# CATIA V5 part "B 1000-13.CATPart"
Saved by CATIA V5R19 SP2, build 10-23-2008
Part number: B 1000-13
Bounding box of the stored display mesh (mm): x -24.865 to 24.865, y -24.997 to 24.997, z 0 to 120.4
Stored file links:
  C:\Users\Bora\Desktop\3D Katı model\B serisi\B 1000\B 1000-13.CATPart
  C:\Program Files\Dassault Systemes\B19\intel_a\reffiles\standard\MetricThickPitch.txt
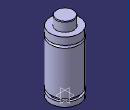
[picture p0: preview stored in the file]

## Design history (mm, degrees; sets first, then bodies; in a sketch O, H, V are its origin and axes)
Body1 (main body)
  Sketch1 on yz-plane, origin (0, 0, 0), H (0, 1, 0), V (0, 0, 1)
    point P3 (15, 119.4)
    point P5 (15, 119.4)
    point P10 (25, 87.9)
    point P11 (25, 91.9)
    point P13 (25, 91.9)
    point P14 (25, 87.9)
    line L1 (25, 0) -> (25, 8)
    line L2 (15, 119.4) -> (15, 104.4)
    arc A1 centre (14, 119.4) radius 1 from (15, 119.4) to (14, 120.4) ccw
    line L3 (21.5, 13) -> (21.5, 8)
    line L4 (25, 13) -> (25, 87.9)
    line L5 (25, 91.9) -> (25, 104.4)
    arc A2 centre (25, 89.9) radius 2 from (25, 91.9) to (25, 87.9) ccw
    line L6 (14, 120.4) -> (0, 120.4)
    point P15 (0, 120.4)
    line L7 (15, 104.4) -> (25, 104.4)
    line L8 (0, 0) -> (25, 0)
    line L9 (21.5, 13) -> (25, 13)
    line L10 (21.5, 8) -> (25, 8)
    coincidence: P15 V, P3 P5, P10 P14, P11 P13
    tangency: L6 A1
    horizontal: L7 H, L8 H, L9 H, L10 H
  Shaft1: profile Sketch1, axis Sketch1.V, angle 360
  Sketch2 on face of Shaft1 from Sketch1.L8, origin (0, 0, 0), H (1, 0, 0), V (0, -1, 0)
    point P1 (10, 0)
    distance P1 V = 10
  Hole1: placed by Sketch2, at (10, 0, 0) direction (0, 0, 1), diameter 6.647, depth 13, threaded "M8", thread diameter 8, thread depth 13, pitch 1.25
  CircPattern1: of Hole1, instances 2, angular step 180, axis from xy-plane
